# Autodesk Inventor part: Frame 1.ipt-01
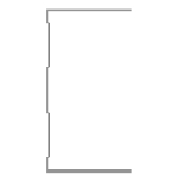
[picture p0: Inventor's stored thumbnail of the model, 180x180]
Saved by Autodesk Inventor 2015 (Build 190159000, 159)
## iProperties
Created: 2015-04
Part Number: Frame 1.ipt-01
Material: Aluminum 6061
Description: Kévin Novo
Document SubType Name: Modeling
Standard: Kevin
Designer: suporte
Standards Organization: Kevin
Language: en-US
Size Designation: (Unnamed 1)
Categories: <MemberInstance><Categories><Category DisplayName="Structural Shapes" InternalName="089c4875-fa83-4c05-b084-43b9cc11f5ed" Mnemonic="GRDR"><CategoryParameter Dis
Density: 2.7 g/cm^3
Appearance: Aluminum - Flat
IsCustomPart: 1
_CCFamilyMember: 1
_CCFamilyDisplayName: Kévin - Kévin Novo
_FrameMemberDoc: Frame Member File
_Version: 15.0.0
_GetPNFromCC: 1
G_L: 887,500 mm
G_W: 50,000 mm
G_H: 75,000 mm
+CD158B76-96DA-4E1F-8CF4-6354A92EFD69+CUTDETAIL1: Cut
+7265168C-F2D8-4F87-8C82-567C4FE17BF0+CUTDETAIL2: Notch
Author: suporte
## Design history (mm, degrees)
node "Start Plane"
node "End Plane"
sketch "Sketch"
  geometry: L1 (24.7, 37.5)-(24.7, 36.9); L2 (24.7, 36.9)-(-24.7, 36.9); L3 (-24.7, -36.9)-(24.7, -36.9); L4 (24.7, -36.9)-(24.7, -37.5); L5 (24.7, -37.5)-(-25.3, -37.5); L6 (-25.3, 37.5)-(24.7, 37.5); L7 (-24.7, 36.9)-(-24.7, 31.9); L8 (-24.7, 31.9)-(-23.3, 30.5); L9 (-23.3, 30.5)-(-23.3, 10.934); L10 (-23.3, 10.934)-(-24.7, 9.534); L11 (-24.7, 9.534)-(-24.7, -9.534); L12 (-24.7, -9.534)-(-23.3, -10.934); L13 (-23.3, -10.934)-(-23.3, -30.5); L14 (-23.3, -30.5)-(-24.7, -31.9); L15 (-24.7, -31.9)-(-24.7, -36.9); L16 (-25.3, -37.5)-(-25.3, -31.651); L17 (-25.3, -31.651)-(-23.9, -30.251); L18 (-23.9, -30.251)-(-23.9, -11.183); L19 (-23.9, -11.183)-(-25.3, -9.783); L20 (-25.3, -9.783)-(-25.3, 9.783); L21 (-25.3, 9.783)-(-23.9, 11.183); L22 (-23.9, 11.183)-(-23.9, 30.251); L23 (-23.9, 30.251)-(-25.3, 31.651); L24 (-25.3, 31.651)-(-25.3, 37.5); L25 (-25.3, 0)-(30.37, 0); 3 further points
  constraints: 50 end point, 10 point on line, 9 parallel, 5 perpendicular, 4 equal length, 3 midpoint, 3 vertical, 2 vertical alignment, 1 collinear, 1 horizontal, 1 horizontal alignment
  dimensions: "d3" = 0.6 distance of L1.start L1.end (= d6); "d5" = 75 distance between parallel lines of L5 L6; "d6" = 0.6 distance between parallel lines of L24 L7 (= d8); "d7" = 0.6 distance between parallel lines of L8 L23 (= d8); "d8" = 0.6 distance between parallel lines of L22 L9 (= d12); "Espessura" = 0.6 distance between parallel lines of L17 L14; "d10" = 0.6 distance between parallel lines of L13 L18 (= Espessura); "d11" = 0.6 distance between parallel lines of L12 L19 (= Espessura); "d12" = 0.6 distance between parallel lines of L21 L10 (= d11); "d13" = 5 distance of L2.end L7.end; "d15" = 135 deg angle of L9 L8; "d16" = 2 distance between parallel lines of L24 L9; "d17" = 50 distance of L6.start L1.start
extrude "Body" join sketch "Sketch" stored distance "d24" = 0.13; taper "d25" = 0 deg
node "Driven Length"
  sketch "Sketch10"
    geometry: L1 (0, 0)-(10, 0) reference
    constraints: 2 end point, 1 horizontal
  workplane "Work Plane7"
  sketch "Sketch11"
    geometry: L1 (-2, 0)-(12, 0) reference; L2 (-2, 887.5)-(12, 887.5) reference
    dimensions: "d27" = 887.5 distance between parallel lines of L1 L2 (derived)
workplane "Work Plane8"
split "Split1"
workplane "Work Plane9"
workplane "Work Plane10"
workplane "Work Plane11"
sketch "Sketch12"
  geometry: L1 (24.7, 37.5)-(24.7, 36.9); L2 (24.7, 36.9)-(-24.7, 36.9); L3 (-24.7, 36.9)-(-24.7, 31.9); L4 (-24.7, 31.9)-(-23.3, 30.5); L5 (-23.3, 30.5)-(-23.3, 10.934); L6 (-23.3, 10.934)-(-24.7, 9.534); L7 (-24.7, 9.534)-(-24.7, -9.534); L8 (-24.7, -9.534)-(-23.3, -10.934); L9 (-23.3, -10.934)-(-23.3, -30.5); L10 (-23.3, -30.5)-(-24.7, -31.9); L11 (-24.7, -31.9)-(-24.7, -36.9); L12 (-24.7, -36.9)-(24.7, -36.9); L13 (24.7, -36.9)-(24.7, -37.5); L14 (24.7, -37.5)-(-25.3, -37.5); L15 (-25.3, -37.5)-(-25.3, -31.651); L16 (-25.3, -31.651)-(-23.9, -30.251); L17 (-23.9, -30.251)-(-23.9, -11.183); L18 (-23.9, -11.183)-(-25.3, -9.783); L19 (-25.3, -9.783)-(-25.3, 9.783); L20 (-25.3, 9.783)-(-23.9, 11.183); L21 (-23.9, 11.183)-(-23.9, 30.251); L22 (-23.9, 30.251)-(-25.3, 31.651); L23 (-25.3, 31.651)-(-25.3, 37.5); L24 (-25.3, 37.5)-(24.7, 37.5)
  constraints: 48 end point, 10 point on line
extrude "Extrusion3" cut sketch "Sketch12" stored distance "d36" = 0.13; taper "d37" = 0 deg
body "Solid1"
other parameters: "G_OFFSET_START" = 0 [user parameter; used in 1 equation term], "G_OFFSET_END" = -12.5 [user parameter; used in 1 equation term], "d22" = 0 (computed from G_OFFSET_START), "d23" = 887.5 (= tamanho + G_OFFSET_END), "G_L" = 887.5 (= d27) [user parameter], "d34" = 90 deg
